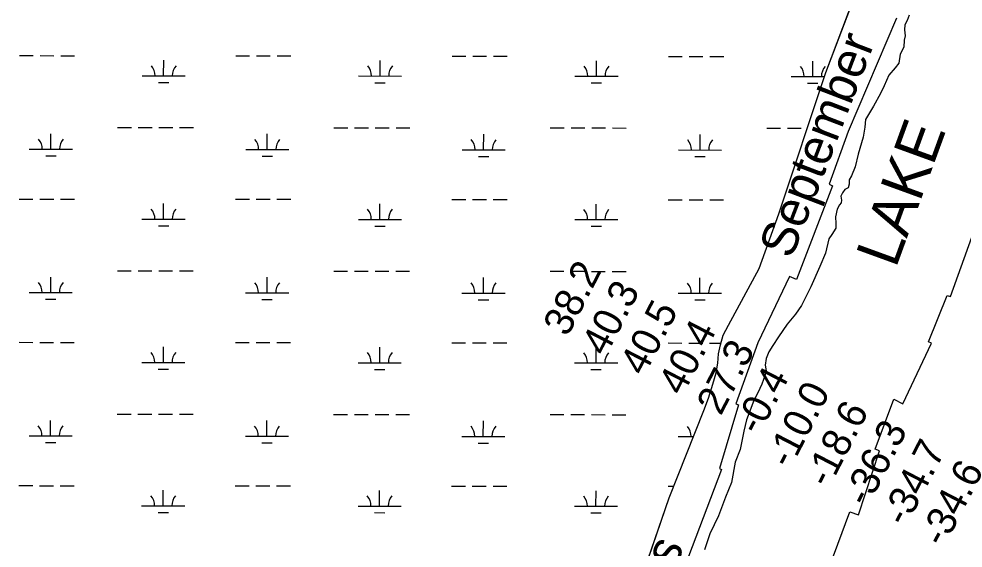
# Model space of a CAD drawing. Extents: x 3148686 to 3186545, y 916144 to 941516.
# Drawn here: x 3157665 to 3159855, y 928658 to 929886 of the extents above; entities that cross this region are included whole.
import ezdxf

# ---------------------------------------------------------------- set-up
doc = ezdxf.new("R2010")
doc.units = 0
for name, color, linetype in [('V-RIVR-EDGE', 7, 'Continuous'), ('V-RIVR-IDEN', 7, 'Continuous'), ('V-RIVR-RANG', 7, 'Continuous'), ('V-RRAP-RVMT', 7, 'Continuous'), ('V-RRAP-RVMT-IDEN', 7, 'Continuous'), ('V-SITE-VEGE', 7, 'Continuous'), ('V-WETL-SWMP', 7, 'Continuous')]:
    doc.layers.add(name, color=color, linetype=linetype)

msp = doc.modelspace()

# ---------------------------------------------------------------- linework, layer by layer
at = {"layer": 'V-RIVR-EDGE'}
for points in [[(3159729.9, 929894.8), (3159725.6, 929882.8), (3159719.9, 929872.2), (3159719.2, 929860.8), (3159720.5, 929847), (3159718.7, 929837.1), (3159718, 929820.8), (3159709.4, 929804.5), (3159705.8, 929783.2), (3159697.7, 929772.6), (3159683.1, 929755.6), (3159671.7, 929730.5), (3159663.8, 929713.1), (3159647.4, 929683.7), (3159628.9, 929652.6), (3159627.1, 929634.8), (3159623.5, 929611.8), (3159611.4, 929572.5), (3159604.5, 929543), (3159596, 929522.1), (3159591, 929512.9), (3159591, 929502.7), (3159588.8, 929494.2), (3159580.7, 929489.9), (3159575.7, 929482.8), (3159571.7, 929474.7), (3159573.1, 929465.1), (3159572.4, 929459.4), (3159568.5, 929454.8), (3159562.8, 929444.6), (3159558.9, 929426.5), (3159560.2, 929410.9)], [(3159560.2, 929410.9), (3159560.2, 929400.6), (3159550.6, 929385.4), (3159543.5, 929375.8), (3159536.3, 929342.2), (3159522.8, 929311.3), (3159502.1, 929264.6), (3159480.3, 929221), (3159466.8, 929200.5), (3159447.3, 929177.5), (3159427.3, 929148.1), (3159413.8, 929128.3), (3159404.6, 929113.1), (3159398.5, 929097.8), (3159396, 929082.6), (3159398.1, 929069.5), (3159395.9, 929060.3), (3159388.1, 929038.6), (3159379.1, 929018.5), (3159369.5, 929000.4), (3159353.1, 928955.8), (3159346.7, 928929.5), (3159338, 928886.3), (3159326.6, 928857.6), (3159317.6, 928809.7), (3159304.1, 928776.4), (3159288, 928732.9), (3159267.7, 928690.7), (3159255.5, 928653.9)]]:
    msp.add_lwpolyline(points, dxfattribs=at)
at = {"layer": 'V-RRAP-RVMT'}
for points in [[(3159700.8, 929887.8), (3159588.4, 929624.9), (3159544.2, 929502.3), (3159552.1, 929498.7), (3159468.4, 929281.2), (3159452.2, 929288.6), (3159379.4, 929134.6), (3159328.3, 928993), (3159334.3, 928990.5), (3159290.1, 928842.3), (3159294.7, 928840.5), (3159192.8, 928570.8)], [(3159488.8, 928462.8), (3159592.8, 928742), (3159612.8, 928735.4), (3159660.9, 928883.5), (3159651, 928887.3), (3159694.7, 929003.7), (3159715.5, 928992.8), (3159781.8, 929133.2), (3159774.8, 929136.8), (3159818.3, 929244.3), (3159826.1, 929241.7), (3159875.8, 929379.4)]]:
    msp.add_lwpolyline(points, dxfattribs=at)
at = {"layer": 'V-SITE-VEGE'}
for p, q in [((3159536.5, 929761.4), (3159623.1, 929989.7)), ((3159427.9, 929433.5), (3159536.5, 929761.4)), ((3159382.5, 929306.4), (3159427.9, 929433.5)), ((3159310.9, 929175), (3159382.5, 929306.4)), ((3159298.9, 929151.9), (3159310.9, 929175)), ((3159292.6, 929129.5), (3159298.9, 929151.9)), ((3159287.9, 929108.5), (3159292.6, 929129.5)), ((3159282.5, 929064.7), (3159286.4, 929086.9)), ((3159286.4, 929086.9), (3159287.9, 929108.5)), ((3159275, 929038.5), (3159282.5, 929064.7)), ((3159264.9, 929005.7), (3159275, 929038.5)), ((3159253.9, 928977.3), (3159264.9, 929005.7)), ((3159173.5, 928774.8), (3159253.9, 928977.3)), ((3159058.9, 928441.6), (3159173.5, 928774.8))]:
    msp.add_line(p, q, dxfattribs=at)
at = {"layer": 'V-WETL-SWMP'}
for p, q in [((3157666.1, 929800.8), (3157698.1, 929800.8)), ((3157714.1, 929800.8), (3157746.1, 929800.7)), ((3157762.1, 929800.7), (3157794.1, 929800.7)), ((3158000.8, 929754), (3158000.9, 929790)), ((3158168, 929800.3), (3158200, 929800.2)), ((3158216, 929800.2), (3158248, 929800.2)), ((3158264, 929800.2), (3158296, 929800.1)), ((3158502.8, 929753.5), (3158502.8, 929789.5)), ((3158669.9, 929799.8), (3158701.9, 929799.7)), ((3158717.9, 929799.7), (3158749.9, 929799.7)), ((3158765.9, 929799.7), (3158797.9, 929799.6)), ((3159004.7, 929753), (3159004.7, 929789)), ((3159171.8, 929799.2), (3159203.8, 929799.2)), ((3159219.8, 929799.2), (3159251.8, 929799.1)), ((3159267.8, 929799.1), (3159299.8, 929799.1)), ((3159506.6, 929752.4), (3159506.6, 929788.4)), ((3157950.8, 929754.1), (3158050.8, 929754)), ((3158452.8, 929753.6), (3158552.8, 929753.4)), ((3158954.7, 929753), (3159054.7, 929752.9)), ((3159456.6, 929752.5), (3159533.5, 929752.4)), ((3157988.8, 929738.6), (3158012.8, 929738.6)), ((3158490.7, 929738.1), (3158514.7, 929738.1)), ((3158992.6, 929737.6), (3159016.6, 929737.5)), ((3159494.6, 929737), (3159518.6, 929737)), ((3157739.2, 929583.5), (3157739.3, 929619.5)), ((3157893.9, 929634.1), (3157925.9, 929634)), ((3157941.9, 929634), (3157973.9, 929634)), ((3157989.9, 929634), (3158021.9, 929633.9)), ((3158037.9, 929633.9), (3158069.9, 929633.9)), ((3158241.1, 929583), (3158241.2, 929619)), ((3158395.8, 929633.5), (3158427.8, 929633.5)), ((3158443.8, 929633.5), (3158475.8, 929633.5)), ((3158491.8, 929633.4), (3158523.8, 929633.4)), ((3158539.8, 929633.4), (3158571.8, 929633.4)), ((3158743, 929582.4), (3158743.1, 929618.4)), ((3158897.7, 929633), (3158929.7, 929633)), ((3158945.7, 929633), (3158977.7, 929632.9)), ((3158993.7, 929632.9), (3159025.7, 929632.9)), ((3159041.7, 929632.9), (3159073.7, 929632.8)), ((3159245, 929581.9), (3159245, 929617.9)), ((3159399.6, 929632.5), (3159431.6, 929632.4)), ((3159447.6, 929632.4), (3159479.6, 929632.4)), ((3157689.2, 929583.5), (3157789.2, 929583.4)), ((3158191.1, 929583), (3158291.1, 929582.9)), ((3158693, 929582.5), (3158793, 929582.4)), ((3159195, 929582), (3159295, 929581.8)), ((3157727.2, 929568.1), (3157751.2, 929568)), ((3158229.1, 929567.5), (3158253.1, 929567.5)), ((3158731, 929567), (3158755, 929567)), ((3159232.9, 929566.5), (3159256.9, 929566.5)), ((3157665.7, 929468.1), (3157697.7, 929468.1)), ((3157713.7, 929468.1), (3157745.7, 929468.1)), ((3157761.7, 929468), (3157793.7, 929468)), ((3158167.6, 929467.6), (3158199.6, 929467.6)), ((3158215.6, 929467.6), (3158247.6, 929467.5)), ((3158263.6, 929467.5), (3158295.6, 929467.5)), ((3158669.5, 929467.1), (3158701.5, 929467)), ((3158717.5, 929467), (3158749.5, 929467)), ((3158765.5, 929467), (3158797.5, 929466.9)), ((3159171.4, 929466.5), (3159203.4, 929466.5)), ((3159219.4, 929466.5), (3159251.4, 929466.5)), ((3159267.4, 929466.4), (3159299.4, 929466.4)), ((3158000.5, 929421.4), (3158000.5, 929457.4)), ((3158502.4, 929420.8), (3158502.4, 929456.8)), ((3159004.3, 929420.3), (3159004.4, 929456.3)), ((3157950.5, 929421.4), (3158050.5, 929421.3)), ((3158452.4, 929420.9), (3158552.4, 929420.8)), ((3158954.3, 929420.3), (3159054.3, 929420.2)), ((3157988.5, 929405.9), (3158012.5, 929405.9)), ((3158490.4, 929405.4), (3158514.4, 929405.4)), ((3158992.3, 929404.9), (3159016.3, 929404.9)), ((3157738.9, 929250.8), (3157738.9, 929286.8)), ((3157893.5, 929301.4), (3157925.5, 929301.4)), ((3157941.5, 929301.3), (3157973.5, 929301.3)), ((3157989.5, 929301.3), (3158021.5, 929301.3)), ((3158037.5, 929301.2), (3158069.5, 929301.2)), ((3158240.8, 929250.3), (3158240.8, 929286.3)), ((3158395.4, 929300.9), (3158427.4, 929300.8)), ((3158443.4, 929300.8), (3158475.4, 929300.8)), ((3158491.4, 929300.8), (3158523.4, 929300.7)), ((3158539.4, 929300.7), (3158571.4, 929300.7)), ((3158742.7, 929249.8), (3158742.7, 929285.8)), ((3158897.3, 929300.3), (3158929.3, 929300.3)), ((3158945.3, 929300.3), (3158977.3, 929300.3)), ((3158993.3, 929300.2), (3159025.3, 929300.2)), ((3159041.3, 929300.2), (3159073.3, 929300.2)), ((3159244.6, 929249.2), (3159244.6, 929285.2)), ((3157688.9, 929250.9), (3157788.9, 929250.8)), ((3158190.8, 929250.3), (3158290.8, 929250.2)), ((3158692.7, 929249.8), (3158792.7, 929249.7)), ((3159194.6, 929249.3), (3159294.6, 929249.2)), ((3157726.9, 929235.4), (3157750.9, 929235.4)), ((3158228.8, 929234.9), (3158252.8, 929234.8)), ((3158730.7, 929234.3), (3158754.7, 929234.3)), ((3159232.6, 929233.8), (3159256.6, 929233.8)), ((3157665.4, 929135.5), (3157697.4, 929135.4)), ((3157713.4, 929135.4), (3157745.4, 929135.4)), ((3157761.4, 929135.4), (3157793.4, 929135.3)), ((3158167.3, 929134.9), (3158199.3, 929134.9)), ((3158215.3, 929134.9), (3158247.3, 929134.8)), ((3158263.3, 929134.8), (3158295.3, 929134.8)), ((3158669.2, 929134.4), (3158701.2, 929134.4)), ((3158717.2, 929134.4), (3158749.2, 929134.3)), ((3158765.2, 929134.3), (3158797.2, 929134.3)), ((3159171.1, 929133.9), (3159203.1, 929133.8)), ((3159219.1, 929133.8), (3159251.1, 929133.8)), ((3159267.1, 929133.8), (3159293.8, 929133.7)), ((3158000.1, 929088.7), (3158000.2, 929124.7)), ((3158502.1, 929088.1), (3158502.1, 929124.1)), ((3159004, 929087.6), (3159004, 929123.6)), ((3157950.1, 929088.7), (3158050.1, 929088.6)), ((3158452.1, 929088.2), (3158552.1, 929088.1)), ((3158954, 929087.7), (3159054, 929087.6)), ((3157988.1, 929073.3), (3158012.1, 929073.2)), ((3158490, 929072.7), (3158514, 929072.7)), ((3158991.9, 929072.2), (3159015.9, 929072.2)), ((3157893.2, 928968.7), (3157925.2, 928968.7)), ((3157941.2, 928968.7), (3157973.2, 928968.6)), ((3157989.2, 928968.6), (3158021.2, 928968.6)), ((3158037.2, 928968.6), (3158069.2, 928968.5)), ((3158395.1, 928968.2), (3158427.1, 928968.2)), ((3158443.1, 928968.1), (3158475.1, 928968.1)), ((3158491.1, 928968.1), (3158523.1, 928968.1)), ((3158539.1, 928968), (3158571.1, 928968)), ((3158897, 928967.7), (3158929, 928967.6)), ((3158945, 928967.6), (3158977, 928967.6)), ((3158993, 928967.6), (3159025, 928967.5)), ((3159041, 928967.5), (3159073, 928967.5)), ((3157738.5, 928918.1), (3157738.6, 928954.1)), ((3158240.4, 928917.6), (3158240.5, 928953.6)), ((3158742.3, 928917.1), (3158742.4, 928953.1)), ((3157688.5, 928918.2), (3157788.5, 928918.1)), ((3158190.4, 928917.7), (3158290.4, 928917.6)), ((3158692.3, 928917.1), (3158792.3, 928917)), ((3159194.3, 928916.6), (3159229.8, 928916.6)), ((3157726.5, 928902.7), (3157750.5, 928902.7)), ((3158228.4, 928902.2), (3158252.4, 928902.2)), ((3158730.3, 928901.7), (3158754.3, 928901.6)), ((3157665, 928802.8), (3157697, 928802.8)), ((3157713, 928802.7), (3157745, 928802.7)), ((3157761, 928802.7), (3157793, 928802.7)), ((3158166.9, 928802.3), (3158198.9, 928802.2)), ((3158214.9, 928802.2), (3158246.9, 928802.2)), ((3158262.9, 928802.2), (3158294.9, 928802.1)), ((3157999.8, 928756), (3157999.8, 928792)), ((3158501.7, 928755.5), (3158501.7, 928791.5)), ((3158668.8, 928801.7), (3158700.8, 928801.7)), ((3158716.8, 928801.7), (3158748.8, 928801.6)), ((3158764.8, 928801.6), (3158796.8, 928801.6)), ((3159003.6, 928754.9), (3159003.7, 928790.9)), ((3159170.7, 928801.2), (3159184, 928801.2)), ((3157949.8, 928756.1), (3158049.8, 928755.9)), ((3157987.8, 928740.6), (3158011.8, 928740.6)), ((3158451.7, 928755.5), (3158551.7, 928755.4)), ((3158489.7, 928740.1), (3158513.7, 928740)), ((3158953.6, 928755), (3159053.6, 928754.9)), ((3158991.6, 928739.5), (3159015.6, 928739.5))]:
    msp.add_line(p, q, dxfattribs=at)
msp.add_lwpolyline([(3159058.9, 928441.6), (3159173.5, 928774.8), (3159253.9, 928977.3), (3159264.9, 929005.7), (3159275, 929038.5), (3159282.5, 929064.7), (3159286.4, 929086.9), (3159287.9, 929108.5), (3159292.6, 929129.5), (3159298.9, 929151.9), (3159310.9, 929175), (3159382.5, 929306.4), (3159427.9, 929433.5), (3159536.5, 929761.4), (3159623.1, 929989.7)], dxfattribs=at)
for centre, start, end in [((3157945.6, 929754.6), 359.1678, 40.7115), ((3158056.1, 929754.4), 139.1678, 180.7115), ((3158447.5, 929754), 359.1678, 40.7115), ((3158558, 929753.9), 139.1678, 180.7115), ((3158949.4, 929753.5), 359.1678, 40.7115), ((3159059.9, 929753.4), 139.1678, 180.7115), ((3159451.3, 929753), 359.1678, 40.7115), ((3159561.8, 929752.9), 139.1678, 180.7115), ((3157684, 929584), 359.1678, 40.7115), ((3157794.5, 929583.9), 139.1678, 180.7115), ((3158185.9, 929583.5), 359.1678, 40.7115), ((3158296.4, 929583.4), 139.1678, 180.7115), ((3158687.8, 929583), 359.1678, 40.7115), ((3158798.3, 929582.8), 139.1678, 180.7115), ((3159189.7, 929582.4), 359.1678, 40.7115), ((3159300.2, 929582.3), 139.1678, 180.7115), ((3157945.3, 929421.9), 359.1678, 40.7115), ((3158055.7, 929421.8), 139.1678, 180.7115), ((3158447.2, 929421.4), 359.1678, 40.7115), ((3158557.6, 929421.2), 139.1678, 180.7115), ((3158949.1, 929420.8), 359.1678, 40.7115), ((3159059.6, 929420.7), 139.1678, 180.7115), ((3157683.6, 929251.3), 359.1678, 40.7115), ((3157794.1, 929251.2), 139.1678, 180.7115), ((3158185.5, 929250.8), 359.1678, 40.7115), ((3158296, 929250.7), 139.1678, 180.7115), ((3158687.5, 929250.3), 359.1678, 40.7115), ((3158797.9, 929250.2), 139.1678, 180.7115), ((3159189.4, 929249.8), 359.1678, 40.7115), ((3159299.8, 929249.6), 139.1678, 180.7115), ((3157944.9, 929089.2), 359.1678, 40.7115), ((3158055.4, 929089.1), 139.1678, 180.7115), ((3158446.8, 929088.7), 359.1678, 40.7115), ((3158557.3, 929088.6), 139.1678, 180.7115), ((3158948.7, 929088.2), 359.1678, 40.7115), ((3159059.2, 929088), 139.1678, 180.7115), ((3157683.3, 928918.7), 359.1678, 40.7115), ((3157793.8, 928918.6), 139.1678, 180.7115), ((3158185.2, 928918.1), 359.1678, 40.7115), ((3158295.7, 928918), 139.1678, 180.7115), ((3158687.1, 928917.6), 359.1678, 40.7115), ((3158797.6, 928917.5), 139.1678, 180.7115), ((3159189, 928917.1), 359.1678, 40.7115), ((3157944.6, 928756.5), 359.1678, 40.7115), ((3158055, 928756.4), 139.1678, 180.7115), ((3158446.5, 928756), 359.1678, 40.7115), ((3158556.9, 928755.9), 139.1678, 180.7115), ((3158948.4, 928755.5), 359.1678, 40.7115), ((3159058.9, 928755.4), 139.1678, 180.7115)]:
    msp.add_arc(centre, 35.2, start, end, dxfattribs=at)

# ---------------------------------------------------------------- texts
at = {"layer": 'V-RIVR-IDEN'}
for s, rotation, p in [('September', 69.013, (3159457.2, 929326.7)), ('Photos', 66.2266, (3159070.5, 928344.5))]:
    msp.add_text(s, height=83, rotation=rotation, dxfattribs=at).set_placement(p)
at = {"layer": 'V-RIVR-RANG'}
for s, p in [('38.2', (3158937.4, 929146.3)), ('40.3', (3159026.3, 929100.6)), ('40.5', (3159115.2, 929054.8)), ('40.4', (3159204.2, 929009)), ('27.3', (3159293.1, 928963.2)), ('-0.4', (3159382, 928917.4)), ('-10.0', (3159454.3, 928839.6)), ('-18.6', (3159543.6, 928794.7)), ('-36.3', (3159633.4, 928750.6)), ('-34.7', (3159722.3, 928704.8)), ('-34.6', (3159810.4, 928657.4))]:
    msp.add_text(s, height=67, rotation=62.6183, dxfattribs=at).set_placement(p)
at = {"layer": 'V-RRAP-RVMT-IDEN'}
msp.add_text('LAKE', height=100, rotation=69.9989, dxfattribs=at).set_placement((3159699, 929305.7))

doc.saveas('drawing.dxf')
